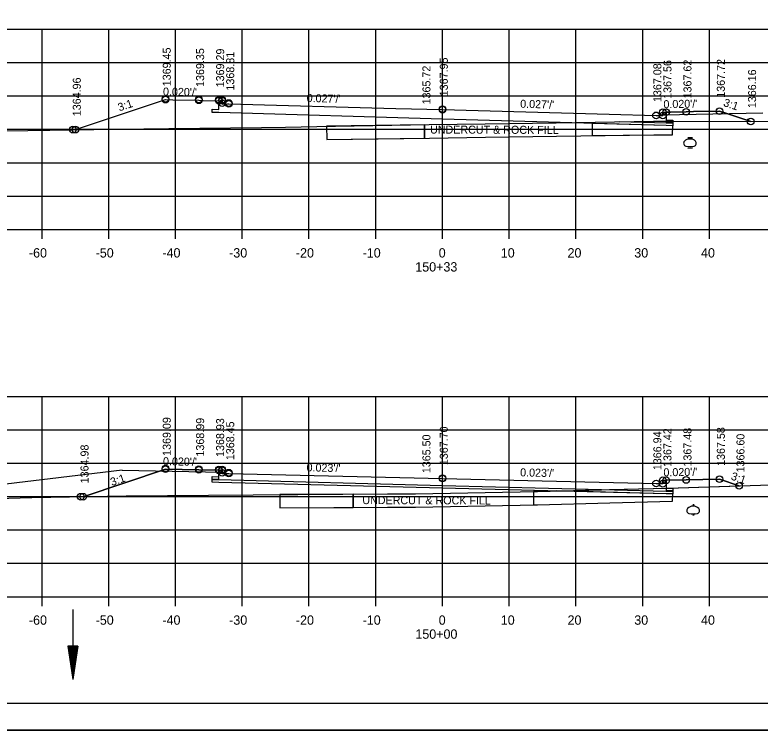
# Model space of a CAD drawing. Extents: x 1374311 to 1383814, y 384102 to 406278.
# Drawn here: x 1381564.6 to 1381676.3, y 391578.1 to 391685.2 of the extents above; entities that cross this region are included whole.
import ezdxf

# ---------------------------------------------------------------- set-up
doc = ezdxf.new("R2010")
doc.units = 0
for name, color, linetype in [('R_Axis', 7, 'Continuous'), ('R_Axis Annot', 7, 'Continuous'), ('R_Border', 7, 'Continuous'), ('R_Draft', 7, 'Continuous'), ('R_Exist Surface', 7, 'Continuous'), ('R_Fin Surface', 7, 'Continuous'), ('R_Grid', 7, 'Continuous'), ('R_No Plot', 7, 'Continuous'), ('R_Water', 7, 'Continuous'), ('R_Xsect Elev', 7, 'Continuous'), ('R_Xsect Slope', 7, 'Continuous')]:
    doc.layers.add(name, color=color, linetype=linetype)

msp = doc.modelspace()

# ---------------------------------------------------------------- linework, layer by layer
at = {"layer": 'R_Axis'}
for p, q in [((1381488.66, 391653.07), (1381768.66, 391653.07)), ((1381568.66, 391651.67), (1381568.66, 391653.07)), ((1381578.66, 391651.67), (1381578.66, 391653.07)), ((1381588.66, 391651.67), (1381588.66, 391653.07)), ((1381598.66, 391651.67), (1381598.66, 391653.07)), ((1381608.66, 391651.67), (1381608.66, 391653.07)), ((1381618.66, 391651.67), (1381618.66, 391653.07)), ((1381628.66, 391651.67), (1381628.66, 391653.07)), ((1381638.66, 391651.67), (1381638.66, 391653.07)), ((1381648.66, 391651.67), (1381648.66, 391653.07)), ((1381658.66, 391651.67), (1381658.66, 391653.07)), ((1381668.66, 391651.67), (1381668.66, 391653.07)), ((1381488.66, 391598.07), (1381768.66, 391598.07)), ((1381568.66, 391596.67), (1381568.66, 391598.07)), ((1381578.66, 391596.67), (1381578.66, 391598.07)), ((1381588.66, 391596.67), (1381588.66, 391598.07)), ((1381598.66, 391596.67), (1381598.66, 391598.07)), ((1381608.66, 391596.67), (1381608.66, 391598.07)), ((1381618.66, 391596.67), (1381618.66, 391598.07)), ((1381628.66, 391596.67), (1381628.66, 391598.07)), ((1381638.66, 391596.67), (1381638.66, 391598.07)), ((1381648.66, 391596.67), (1381648.66, 391598.07)), ((1381658.66, 391596.67), (1381658.66, 391598.07)), ((1381668.66, 391596.67), (1381668.66, 391598.07))]:
    msp.add_line(p, q, dxfattribs=at)
at = {"layer": 'R_Border'}
msp.add_line((1381786.84, 391582.07), (1381470.66, 391582.07), dxfattribs=at)
at = {"layer": 'R_Draft'}
for p, q in [((1381661.66, 391670.26), (1381676.66, 391670.56)), ((1381580.66, 391617.03), (1381538.09, 391611.92)), ((1381580.66, 391617.03), (1381595.65, 391616.73)), ((1381572.55, 391590.66), (1381573.3, 391585.66)), ((1381574.05, 391590.66), (1381572.55, 391590.66)), ((1381572.68, 391590.66), (1381573.3, 391586.49)), ((1381572.81, 391590.66), (1381573.3, 391587.35)), ((1381572.93, 391590.66), (1381573.3, 391588.19)), ((1381573.06, 391590.66), (1381573.3, 391589.03)), ((1381573.19, 391590.66), (1381573.3, 391589.87)), ((1381574.05, 391590.66), (1381573.3, 391585.66)), ((1381573.55, 391590.66), (1381573.3, 391589.03)), ((1381573.8, 391590.66), (1381573.3, 391587.35)), ((1381573.93, 391590.66), (1381573.3, 391586.49)), ((1381573.68, 391590.66), (1381573.3, 391588.19)), ((1381573.42, 391590.66), (1381573.3, 391589.87))]:
    msp.add_line(p, q, dxfattribs=at)
for centre, radius, start, end in [((1381665.75, 391665.49), 1.15, 43.6485, 136.3515), ((1381665.23, 391665.98), 0.438, 136.3515, 253.9529), ((1381665.75, 391667.76), 2.29, 253.9529, 286.0471), ((1381666.26, 391665.98), 0.438, 286.0471, 43.6485), ((1381665.71, 391610.97), 0.438, 136.3515, 253.9529), ((1381666.22, 391610.48), 1.15, 43.6485, 136.3515), ((1381666.74, 391610.97), 0.438, 286.0471, 43.6485), ((1381666.22, 391612.75), 2.29, 253.9529, 286.0471)]:
    msp.add_arc(centre, radius, start, end, dxfattribs=at)
at = {"layer": 'R_Exist Surface'}
for p, q in [((1381666.13, 391666.82), (1381665.41, 391666.81)), ((1381666.13, 391665.24), (1381665.41, 391665.22)), ((1381666.38, 391611.84), (1381666.17, 391611.82)), ((1381666.38, 391610.26), (1381666.17, 391610.24))]:
    msp.add_line(p, q, dxfattribs=at)
for points in [[(1381561.94, 391667.87), (1381566.52, 391667.91), (1381576.45, 391668.06), (1381587.65, 391668.19), (1381601.56, 391668.36), (1381605.14, 391668.4), (1381609.86, 391668.51), (1381626.68, 391668.77), (1381635.08, 391668.89), (1381645.7, 391669.05), (1381660.29, 391669.27), (1381662.39, 391669.27), (1381680.63, 391669.23)], [(1381558.44, 391612.7), (1381567.12, 391612.92), (1381581.28, 391613.17), (1381593.62, 391613.3), (1381620.43, 391613.47), (1381622.45, 391613.47), (1381622.78, 391613.47), (1381624.6, 391613.5), (1381642.88, 391613.83), (1381653.67, 391614.13), (1381662.48, 391614.34), (1381677.87, 391614.83)]]:
    msp.add_lwpolyline(points, dxfattribs=at)
at = {"layer": 'R_Fin Surface'}
for p, q in [((1381625.99, 391668.76), (1381611.31, 391668.53)), ((1381625.99, 391668.76), (1381625.99, 391666.76)), ((1381625.99, 391666.76), (1381625.99, 391668.76)), ((1381651.08, 391668.95), (1381651.08, 391667.13)), ((1381651.08, 391668.95), (1381651.08, 391667.13)), ((1381651.08, 391667.13), (1381660.31, 391667.27)), ((1381615.28, 391613.44), (1381604.27, 391613.36)), ((1381615.28, 391613.44), (1381615.28, 391611.44)), ((1381615.28, 391611.44), (1381615.28, 391613.44)), ((1381642.31, 391613.82), (1381642.31, 391611.82)), ((1381642.31, 391613.82), (1381642.31, 391611.82)), ((1381642.31, 391611.82), (1381642.92, 391611.83))]:
    msp.add_line(p, q, dxfattribs=at)
for points in [[(1381573.67, 391668.03), (1381584.19, 391671.54), (1381587.15, 391672.52), (1381588.26, 391672.5), (1381592.15, 391672.42), (1381592.82, 391672.41), (1381595.15, 391672.36), (1381595.26, 391672.36), (1381595.65, 391672.36), (1381595.65, 391672.25), (1381595.66, 391671.86), (1381596.44, 391671.88), (1381596.66, 391671.88), (1381621.65, 391671.2), (1381628.66, 391671.02), (1381653.65, 391670.34), (1381660.66, 391670.16), (1381661.44, 391670.14), (1381661.66, 391670.14), (1381661.66, 391670.25), (1381661.67, 391670.64), (1381662.06, 391670.64), (1381662.17, 391670.64), (1381662.84, 391670.65), (1381665.17, 391670.7), (1381666.28, 391670.72), (1381670.17, 391670.8), (1381671.13, 391670.48), (1381674.85, 391669.24)], [(1381662.17, 391670.28), (1381662.18, 391669.11), (1381663.18, 391669.1), (1381663.17, 391668.6), (1381662.17, 391668.63), (1381628.66, 391669.6), (1381595.15, 391670.57), (1381594.15, 391670.6), (1381594.16, 391671.1), (1381595.16, 391671.05), (1381595.15, 391672.13)], [(1381663.17, 391668.6), (1381662.17, 391668.63), (1381651.08, 391668.95)], [(1381611.31, 391668.53), (1381611.33, 391666.53), (1381626.71, 391666.77), (1381635.11, 391666.89), (1381645.73, 391667.05), (1381660.31, 391667.27), (1381663.14, 391667.27), (1381663.17, 391668.6)], [(1381611.31, 391668.53), (1381611.33, 391666.53), (1381625.99, 391666.76)], [(1381660.31, 391667.27), (1381663.14, 391667.27), (1381663.17, 391668.6)], [(1381574.83, 391613.05), (1381587.15, 391617.16), (1381592.15, 391617.06), (1381595.15, 391617), (1381595.65, 391617), (1381595.66, 391616.5), (1381596.66, 391616.52), (1381628.66, 391615.77), (1381660.66, 391615.02), (1381661.66, 391615), (1381661.67, 391615.5), (1381662.17, 391615.5), (1381665.17, 391615.56), (1381670.17, 391615.66), (1381673.11, 391614.68)], [(1381662.17, 391615.14), (1381662.18, 391613.98), (1381663.18, 391613.97), (1381663.17, 391613.47), (1381662.17, 391613.49), (1381628.66, 391614.34), (1381595.15, 391615.19), (1381594.15, 391615.22), (1381594.16, 391615.72), (1381595.16, 391615.68), (1381595.15, 391616.76)], [(1381604.27, 391613.36), (1381604.27, 391611.37), (1381620.44, 391611.47), (1381622.45, 391611.47), (1381622.8, 391611.47), (1381624.63, 391611.5), (1381642.92, 391611.83), (1381653.72, 391612.14), (1381663.14, 391612.36), (1381663.17, 391613.47)], [(1381604.27, 391613.36), (1381604.27, 391611.37), (1381615.28, 391611.44)], [(1381645.79, 391613.91), (1381642.88, 391613.83), (1381642.31, 391613.82)], [(1381642.92, 391611.83), (1381653.72, 391612.14), (1381663.14, 391612.36), (1381663.17, 391613.47)], [(1381663.17, 391613.47), (1381662.17, 391613.49), (1381645.79, 391613.91)]]:
    msp.add_lwpolyline(points, dxfattribs=at)
at = {"layer": 'R_Grid'}
for p, q in [((1381488.66, 391683.07), (1381768.66, 391683.07)), ((1381568.66, 391653.07), (1381568.66, 391683.07)), ((1381578.66, 391653.07), (1381578.66, 391683.07)), ((1381588.66, 391653.07), (1381588.66, 391683.07)), ((1381598.66, 391653.07), (1381598.66, 391683.07)), ((1381608.66, 391653.07), (1381608.66, 391683.07)), ((1381618.66, 391653.07), (1381618.66, 391683.07)), ((1381628.66, 391653.07), (1381628.66, 391683.07)), ((1381638.66, 391653.07), (1381638.66, 391683.07)), ((1381648.66, 391653.07), (1381648.66, 391683.07)), ((1381658.66, 391653.07), (1381658.66, 391683.07)), ((1381668.66, 391653.07), (1381668.66, 391683.07)), ((1381488.66, 391678.07), (1381768.66, 391678.07)), ((1381488.66, 391673.07), (1381768.66, 391673.07)), ((1381488.66, 391668.07), (1381768.66, 391668.07)), ((1381488.66, 391663.07), (1381768.66, 391663.07)), ((1381488.66, 391658.07), (1381768.66, 391658.07)), ((1381488.66, 391653.07), (1381768.66, 391653.07)), ((1381488.66, 391628.07), (1381768.66, 391628.07)), ((1381568.66, 391598.07), (1381568.66, 391628.07)), ((1381578.66, 391598.07), (1381578.66, 391628.07)), ((1381588.66, 391598.07), (1381588.66, 391628.07)), ((1381598.66, 391598.07), (1381598.66, 391628.07)), ((1381608.66, 391598.07), (1381608.66, 391628.07)), ((1381618.66, 391598.07), (1381618.66, 391628.07)), ((1381628.66, 391598.07), (1381628.66, 391628.07)), ((1381638.66, 391598.07), (1381638.66, 391628.07)), ((1381648.66, 391598.07), (1381648.66, 391628.07)), ((1381658.66, 391598.07), (1381658.66, 391628.07)), ((1381668.66, 391598.07), (1381668.66, 391628.07)), ((1381488.66, 391623.07), (1381768.66, 391623.07)), ((1381488.66, 391618.07), (1381768.66, 391618.07)), ((1381488.66, 391613.07), (1381768.66, 391613.07)), ((1381488.66, 391608.07), (1381768.66, 391608.07)), ((1381488.66, 391603.07), (1381768.66, 391603.07)), ((1381488.66, 391598.07), (1381768.66, 391598.07))]:
    msp.add_line(p, q, dxfattribs=at)
at = {"layer": 'R_No Plot'}
msp.add_line((1381458.26, 391578.1), (1381791.59, 391578.1), dxfattribs=at)
for points in [[(1381458.25, 391791.43), (1381791.59, 391791.43), (1381791.59, 391578.09), (1381458.25, 391578.09)], [(1381704.58, 391787.53), (1381704.58, 391777.65), (1381740.31, 391777.65), (1381740.31, 391774.73), (1381763.51, 391774.73), (1381763.51, 391751.52), (1381786.84, 391751.52), (1381786.84, 391582.07), (1381470.66, 391582.07), (1381470.66, 391787.53)], [(1381663.18, 391669.27), (1381674.84, 391669.24), (1381671.13, 391670.48), (1381670.17, 391670.8), (1381666.28, 391670.72), (1381665.17, 391670.7), (1381662.84, 391670.65), (1381662.17, 391670.64), (1381662.18, 391669.47), (1381663.18, 391669.46)], [(1381655.13, 391669.19), (1381660.29, 391669.27), (1381662.39, 391669.27), (1381663.18, 391669.27), (1381663.17, 391668.96), (1381662.17, 391668.99)], [(1381574.83, 391613.05), (1381581.28, 391613.17), (1381593.62, 391613.3), (1381620.43, 391613.47), (1381622.45, 391613.47), (1381622.78, 391613.47), (1381624.6, 391613.5), (1381642.88, 391613.83), (1381652.47, 391614.1), (1381628.66, 391614.7), (1381595.15, 391615.55), (1381594.15, 391615.58), (1381594.16, 391616.08), (1381595.16, 391616.04), (1381595.15, 391617), (1381595.15, 391617), (1381592.15, 391617.06), (1381587.15, 391617.16)], [(1381662.39, 391614.34), (1381662.48, 391614.34), (1381673.11, 391614.68), (1381670.17, 391615.66), (1381665.17, 391615.56), (1381662.17, 391615.5), (1381662.18, 391614.34)], [(1381652.47, 391614.1), (1381653.67, 391614.13), (1381662.39, 391614.34), (1381663.18, 391614.33), (1381663.17, 391613.83), (1381662.17, 391613.85)]]:
    msp.add_lwpolyline(points, close=True, dxfattribs=at)
for centre in [(1381587.15, 391672.65), (1381587.15, 391672.65), (1381587.15, 391672.52), (1381592.15, 391672.55), (1381592.15, 391672.55), (1381592.15, 391672.42), (1381595.15, 391672.49), (1381595.15, 391672.49), (1381595.15, 391672.36), (1381595.65, 391672.49), (1381595.65, 391672.49), (1381595.65, 391672.36), (1381595.66, 391671.99), (1381596.66, 391672.01), (1381596.66, 391672.01), (1381596.66, 391671.88), (1381628.66, 391671.08), (1381628.66, 391671.08), (1381628.66, 391671.02), (1381661.67, 391670.64), (1381661.67, 391670.64), (1381661.67, 391670.63), (1381662.17, 391670.64), (1381662.17, 391670.64), (1381662.17, 391670.63), (1381665.17, 391670.7), (1381665.17, 391670.7), (1381665.17, 391670.69), (1381670.17, 391670.8), (1381670.17, 391670.8), (1381670.17, 391670.79), (1381660.66, 391670.16), (1381660.66, 391670.16), (1381660.66, 391670.15), (1381661.66, 391670.14), (1381674.84, 391669.24), (1381674.85, 391669.24), (1381674.85, 391669.24), (1381573.28, 391668.03), (1381573.28, 391668.03), (1381573.28, 391668.03), (1381573.28, 391668.03), (1381573.67, 391668.03), (1381573.67, 391668.03), (1381587.15, 391617.28), (1381587.15, 391617.28), (1381587.15, 391617.16), (1381592.15, 391617.18), (1381592.15, 391617.18), (1381592.15, 391617.06), (1381595.15, 391617.12), (1381595.15, 391617.12), (1381595.15, 391617), (1381595.65, 391617.12), (1381595.65, 391617.12), (1381595.65, 391617), (1381595.66, 391616.62), (1381596.66, 391616.64), (1381596.66, 391616.64), (1381596.66, 391616.52), (1381628.66, 391615.83), (1381628.66, 391615.83), (1381628.66, 391615.77), (1381660.66, 391615.02), (1381660.66, 391615.02), (1381660.66, 391615.02), (1381661.66, 391615), (1381661.67, 391615.5), (1381661.67, 391615.5), (1381661.67, 391615.5), (1381662.17, 391615.5), (1381662.17, 391615.5), (1381662.17, 391615.5), (1381665.17, 391615.56), (1381665.17, 391615.56), (1381665.17, 391615.56), (1381670.17, 391615.66), (1381670.17, 391615.66), (1381670.17, 391615.66), (1381673.11, 391614.68), (1381673.11, 391614.68), (1381673.11, 391614.67), (1381574.46, 391613.05), (1381574.46, 391613.05), (1381574.47, 391613.05), (1381574.47, 391613.05), (1381574.83, 391613.05), (1381574.83, 391613.05)]:
    msp.add_circle(centre, 0.5, dxfattribs=at)
at = {"layer": 'R_Water'}
for p, q in [((1381666.13, 391666.61), (1381665.41, 391666.6)), ((1381666.13, 391665.45), (1381665.41, 391665.43)), ((1381666.38, 391611.63), (1381666.17, 391611.62)), ((1381666.38, 391610.46), (1381666.17, 391610.45)), ((1381573.3, 391596.17), (1381573.3, 391585.66))]:
    msp.add_line(p, q, dxfattribs=at)

# ---------------------------------------------------------------- texts
at = {"layer": 'R_Axis Annot'}
for s, p in [('-60', (1381566.7, 391648.87)), ('-50', (1381576.7, 391648.87)), ('-40', (1381586.7, 391648.87)), ('-30', (1381596.7, 391648.87)), ('-20', (1381606.7, 391648.87)), ('-10', (1381616.7, 391648.87)), ('0', (1381628.1, 391648.87)), ('10', (1381637.4, 391648.87)), ('20', (1381647.4, 391648.87)), ('30', (1381657.4, 391648.87)), ('40', (1381667.4, 391648.87)), ('150+33', (1381624.59, 391646.77)), ('-60', (1381566.7, 391593.87)), ('-50', (1381576.7, 391593.87)), ('-40', (1381586.7, 391593.87)), ('-30', (1381596.7, 391593.87)), ('-20', (1381606.7, 391593.87)), ('-10', (1381616.7, 391593.87)), ('0', (1381628.1, 391593.87)), ('10', (1381637.4, 391593.87)), ('20', (1381647.4, 391593.87)), ('30', (1381657.4, 391593.87)), ('40', (1381667.4, 391593.87)), ('150+00', (1381624.6, 391591.77))]:
    msp.add_text(s, height=1.4, dxfattribs=at).set_placement(p)
at = {"layer": 'R_Fin Surface'}
for p in [(1381626.8, 391667.44), (1381616.65, 391611.94)]:
    msp.add_text('UNDERCUT & ROCK FILL', height=1.2, rotation=359.8099, dxfattribs=at).set_placement(p)
at = {"layer": 'R_Xsect Elev'}
for s, p in [('1369.45', (1381587.95, 391674.52)), ('1369.35', (1381592.95, 391674.42)), ('1369.29', (1381595.95, 391674.36)), ('1368.81', (1381597.46, 391673.88)), ('1367.95', (1381629.46, 391673.02)), ('1367.08', (1381661.46, 391672.16)), ('1367.56', (1381662.97, 391672.64)), ('1367.62', (1381665.97, 391672.7)), ('1367.72', (1381670.97, 391672.8)), ('1365.72', (1381626.86, 391671.8)), ('1366.16', (1381675.65, 391671.24)), ('1364.96', (1381574.47, 391670.03)), ('1369.09', (1381587.95, 391619.16)), ('1368.99', (1381592.95, 391619.06)), ('1368.93', (1381595.95, 391619)), ('1368.45', (1381597.46, 391618.52)), ('1367.70', (1381629.46, 391617.77)), ('1367.42', (1381662.97, 391617.5)), ('1367.48', (1381665.97, 391617.56)), ('1367.58', (1381670.97, 391617.66)), ('1365.50', (1381626.86, 391616.57)), ('1366.94', (1381661.46, 391617.02)), ('1366.60', (1381673.91, 391616.68)), ('1364.98', (1381575.63, 391615.05))]:
    msp.add_text(s, height=1.2, rotation=90, dxfattribs=at).set_placement(p)
at = {"layer": 'R_Xsect Slope'}
for s, rotation, p in [("0.020'/'", 358.8542, (1381586.78, 391673.13)), ("0.027'/'", 358.4533, (1381608.3, 391672.17)), ('3:1', 18.435, (1381580.25, 391670.75)), ("0.027'/'", 358.4533, (1381640.3, 391671.31)), ("0.020'/'", 1.1458, (1381661.78, 391671.23)), ('3:1', 341.5651, (1381670.66, 391671.59)), ("0.020'/'", 358.8542, (1381586.78, 391617.77)), ("0.023'/'", 358.6549, (1381608.29, 391616.85)), ("0.020'/'", 1.1458, (1381661.78, 391616.09)), ('3:1', 18.4349, (1381579.13, 391614.64)), ("0.023'/'", 358.6549, (1381640.29, 391616.1)), ('3:1', 341.5651, (1381671.8, 391615.64))]:
    msp.add_text(s, height=1.2, rotation=rotation, dxfattribs=at).set_placement(p)

doc.saveas('drawing.dxf')
